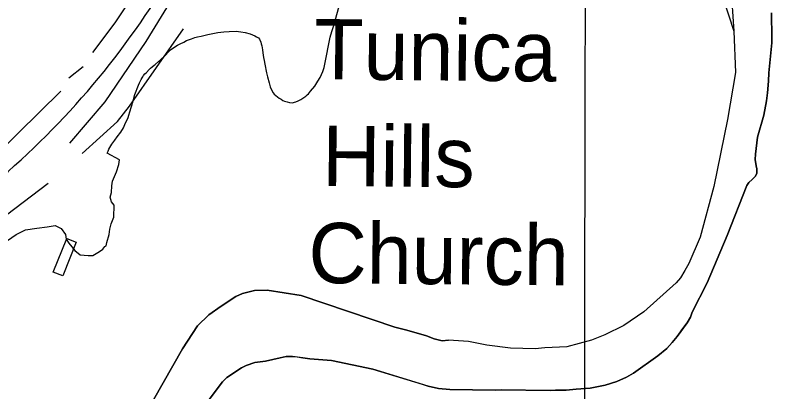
# Model space of a CAD drawing. Extents: x 3192986 to 3230865, y 867483 to 892886.
# Drawn here: x 3217338 to 3218379, y 886066 to 886585 of the extents above; entities that cross this region are included whole.
import ezdxf

# ---------------------------------------------------------------- set-up
doc = ezdxf.new("R2010")
doc.units = 0
for name, color, linetype in [('V-BLDG-OTLN', 7, 'Continuous'), ('V-GRID-MAJR', 7, 'Continuous'), ('V-ROAD-CNTR', 7, 'Continuous'), ('V-SITE-OTLN-IDEN', 7, 'Continuous'), ('V-SITE-VEGE', 7, 'Continuous'), ('V-TOPO-SHOR', 7, 'Continuous')]:
    doc.layers.add(name, color=color, linetype=linetype)

msp = doc.modelspace()

# ---------------------------------------------------------------- linework, layer by layer
at = {"layer": 'V-BLDG-OTLN'}
msp.add_lwpolyline([(3217422.247118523, 886272.3664276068), (3217403.836155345, 886225.8805205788), (3217390.820181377, 886231.035510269), (3217409.2311445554, 886277.5224172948)], close=True, dxfattribs=at)
at = {"layer": 'V-GRID-MAJR'}
msp.add_spline([(3218098.305, 872881.337), (3218108.882, 878940.914), (3218119.463, 885003.5750000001), (3218130.045, 891066.2810000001), (3218130.0500000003, 891069.3200000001)], degree=3, dxfattribs=at)
at = {"layer": 'V-ROAD-CNTR'}
msp.add_arc((3216590.678657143, 887208.6877788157), 1117.3858142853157, 308.27081185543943, 327.8519812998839, dxfattribs=at)
at = {"layer": 'V-SITE-VEGE'}
for p, q in [((3218120.414000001, 887211.4949999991), (3218326.171000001, 886562.636999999)), ((3217776.328000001, 886570.2949999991), (3217785.761000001, 886603.991999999)), ((3218377.999, 886587.9949999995), (3218378.196, 886576.0699999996)), ((3218378.196, 886576.0699999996), (3218378.542, 886565.1989999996)), ((3217616.9650000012, 886560.684999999), (3217625.449000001, 886561.952999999)), ((3217625.449000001, 886561.952999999), (3217632.712000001, 886562.4339999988)), ((3217632.712000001, 886562.4339999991), (3217642.184000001, 886562.476999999)), ((3217642.184000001, 886562.476999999), (3217648.420000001, 886561.768999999)), ((3217648.420000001, 886561.768999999), (3217654.648000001, 886560.6549999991)), ((3217771.625000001, 886554.2529999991), (3217773.770000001, 886562.0759999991)), ((3217773.770000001, 886562.0759999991), (3217776.328000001, 886570.2949999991)), ((3218326.171000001, 886562.636999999), (3218328.659000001, 886505.8929999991)), ((3218378.542, 886565.1989999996), (3218378.6550000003, 886556.0549999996)), ((3217574.057000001, 886549.7179999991), (3217580.750000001, 886552.224999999)), ((3217580.750000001, 886552.224999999), (3217585.208000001, 886553.7629999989)), ((3217585.208000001, 886553.7629999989), (3217589.056000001, 886554.9079999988)), ((3217589.056000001, 886554.9079999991), (3217593.908000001, 886555.8339999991)), ((3217593.908000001, 886555.8339999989), (3217603.016000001, 886558.0989999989)), ((3217603.016000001, 886558.0989999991), (3217616.9650000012, 886560.684999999)), ((3217654.648000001, 886560.6549999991), (3217661.2690000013, 886558.9319999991)), ((3217661.2690000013, 886558.9319999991), (3217664.677000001, 886557.866999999)), ((3217664.677000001, 886557.866999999), (3217667.880000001, 886556.4029999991)), ((3217667.880000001, 886556.4029999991), (3217670.272000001, 886554.9509999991)), ((3217670.272000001, 886554.9509999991), (3217672.668000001, 886553.7019999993)), ((3217672.668000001, 886553.7019999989), (3217674.448000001, 886551.6559999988)), ((3217674.448000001, 886551.6559999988), (3217676.193000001, 886547.596999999)), ((3217769.012000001, 886542.809999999), (3217771.625000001, 886554.2529999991)), ((3218378.6550000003, 886556.0549999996), (3218378.4930000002, 886546.5209999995)), ((3217552.080000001, 886536.9899999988), (3217557.792000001, 886541.1269999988)), ((3217557.792000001, 886541.1269999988), (3217561.458000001, 886543.4819999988)), ((3217561.458000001, 886543.481999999), (3217565.115000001, 886545.435999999)), ((3217565.115000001, 886545.4359999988), (3217570.397000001, 886547.7649999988)), ((3217570.397000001, 886547.7649999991), (3217574.057000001, 886549.7179999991)), ((3217676.193000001, 886547.596999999), (3217676.555000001, 886545.1699999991)), ((3217676.555000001, 886545.1699999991), (3217677.315000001, 886542.5399999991)), ((3217677.315000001, 886542.5399999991), (3217678.228000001, 886536.878999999)), ((3217766.358000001, 886528.748999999), (3217769.012000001, 886542.809999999)), ((3218378.4930000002, 886546.5209999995), (3218374.624, 886505.5159999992)), ((3217545.108000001, 886529.8529999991), (3217548.5980000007, 886533.6229999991)), ((3217548.598000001, 886533.6229999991), (3217552.080000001, 886536.9899999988)), ((3217678.228000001, 886536.878999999), (3217678.9700000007, 886533.0389999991)), ((3217678.970000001, 886533.0389999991), (3217679.865000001, 886526.3749999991)), ((3217530.985000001, 886516.988999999), (3217535.284000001, 886520.949999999)), ((3217535.284000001, 886520.949999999), (3217537.531000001, 886522.7259999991)), ((3217537.531000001, 886522.7259999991), (3217545.108000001, 886529.8529999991)), ((3217679.865000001, 886526.3749999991), (3217680.6040000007, 886522.3319999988)), ((3217680.604000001, 886522.3319999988), (3217681.731000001, 886517.476999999)), ((3217763.065000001, 886512.6819999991), (3217766.358000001, 886528.748999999)), ((3217518.708000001, 886505.9139999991), (3217522.6070000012, 886510.0789999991)), ((3217522.6070000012, 886510.0789999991), (3217524.446000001, 886511.6599999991)), ((3217524.446000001, 886511.6599999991), (3217526.898000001, 886513.6349999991)), ((3217526.898000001, 886513.6349999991), (3217529.353000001, 886515.809999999)), ((3217529.353000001, 886515.809999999), (3217530.985000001, 886516.988999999)), ((3217681.731000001, 886517.476999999), (3217683.944000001, 886505.3479999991)), ((3217761.359000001, 886507.0689999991), (3217763.065000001, 886512.6819999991)), ((3217512.736000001, 886498.356999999), (3217513.973000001, 886499.947999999)), ((3217513.973000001, 886499.947999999), (3217515.009000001, 886501.743999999)), ((3217515.009000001, 886501.743999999), (3217516.664000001, 886504.133999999)), ((3217516.664000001, 886504.133999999), (3217518.708000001, 886505.9139999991)), ((3217683.944000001, 886505.3479999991), (3217685.2590000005, 886499.6839999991)), ((3217685.259000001, 886499.6839999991), (3217687.539000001, 886491.3829999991)), ((3217754.684000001, 886493.881999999), (3217757.593000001, 886498.868999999)), ((3217757.593000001, 886498.868999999), (3217761.359000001, 886507.0689999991)), ((3218328.659000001, 886505.8929999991), (3218317.628000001, 886440.8999999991)), ((3218374.624, 886505.5159999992), (3218374.028, 886493.8689999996)), ((3217502.883000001, 886475.5499999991), (3217507.937000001, 886488.562999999)), ((3217507.937000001, 886488.562999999), (3217509.402000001, 886491.763999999)), ((3217509.402000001, 886491.763999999), (3217511.486000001, 886495.957999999)), ((3217511.486000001, 886495.957999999), (3217512.736000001, 886498.356999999)), ((3217687.539000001, 886491.3829999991), (3217689.062000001, 886486.1179999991)), ((3217750.341000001, 886487.1009999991), (3217751.793000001, 886489.4949999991)), ((3217751.793000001, 886489.4949999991), (3217754.684000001, 886493.881999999)), ((3218374.028, 886493.8689999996), (3218372.8340000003, 886477.9909999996)), ((3217689.062000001, 886486.1179999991), (3217690.6070000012, 886482.060999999)), ((3217690.6070000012, 886482.060999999), (3217693.156000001, 886477.986999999)), ((3217693.156000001, 886477.986999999), (3217694.537000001, 886476.1499999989)), ((3217741.4990000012, 886476.569999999), (3217744.575000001, 886479.944999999)), ((3217744.575000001, 886479.944999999), (3217750.341000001, 886487.1009999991)), ((3218372.8340000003, 886477.9909999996), (3218371.19, 886466.7579999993)), ((3217499.659000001, 886463.712999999), (3217501.380000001, 886470.1329999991)), ((3217501.380000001, 886470.1329999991), (3217501.816000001, 886472.1419999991)), ((3217501.816000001, 886472.1419999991), (3217502.883000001, 886475.5499999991)), ((3217694.537000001, 886476.1499999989), (3217699.1060000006, 886472.2449999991)), ((3217699.106000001, 886472.2449999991), (3217701.295000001, 886470.5959999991)), ((3217701.295000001, 886470.5959999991), (3217703.892000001, 886469.1419999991)), ((3217703.892000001, 886469.1419999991), (3217706.483000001, 886467.484999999)), ((3217727.231000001, 886466.9339999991), (3217730.8870000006, 886468.6869999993)), ((3217730.887000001, 886468.6869999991), (3217733.938000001, 886470.449999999)), ((3217733.938000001, 886470.449999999), (3217738.018000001, 886473.202999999)), ((3217738.018000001, 886473.202999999), (3217739.8630000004, 886475.187999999)), ((3217739.863000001, 886475.1879999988), (3217741.4990000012, 886476.569999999)), ((3217496.026000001, 886451.481999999), (3217497.744000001, 886457.699999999)), ((3217497.744000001, 886457.699999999), (3217499.020000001, 886461.709999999)), ((3217499.020000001, 886461.709999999), (3217499.659000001, 886463.712999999)), ((3217706.483000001, 886467.484999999), (3217708.6780000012, 886466.2399999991)), ((3217708.6780000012, 886466.2399999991), (3217712.295000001, 886465.5739999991)), ((3217712.295000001, 886465.5739999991), (3217715.703000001, 886464.508999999)), ((3217715.703000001, 886464.508999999), (3217719.322000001, 886464.045999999)), ((3217719.322000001, 886464.045999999), (3217724.382000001, 886465.3729999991)), ((3217724.382000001, 886465.3729999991), (3217727.231000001, 886466.9339999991)), ((3218371.19, 886466.7579999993), (3218367.6820000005, 886447.2099999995)), ((3217493.480000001, 886443.866999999), (3217494.545000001, 886447.2729999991)), ((3217494.545000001, 886447.2729999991), (3217496.026000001, 886451.481999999)), ((3218367.682, 886447.2099999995), (3218358.6890000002, 886416.7579999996)), ((3217489.282000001, 886434.0639999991), (3217493.480000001, 886443.866999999)), ((3218317.628000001, 886440.8999999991), (3218298.723000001, 886348.7459999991)), ((3217483.666000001, 886423.4779999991), (3217487.398000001, 886429.6599999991)), ((3217487.398000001, 886429.6599999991), (3217489.282000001, 886434.0639999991)), ((3217475.218000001, 886412.5349999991), (3217478.7290000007, 886417.312999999)), ((3217478.729000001, 886417.312999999), (3217483.666000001, 886423.4779999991)), ((3218358.6890000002, 886416.7579999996), (3218356.176, 886393.3509999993)), ((3217467.354000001, 886400.172999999), (3217471.2960000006, 886406.9579999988)), ((3217471.296000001, 886406.9579999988), (3217475.218000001, 886412.5349999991)), ((3217464.956000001, 886394.8609999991), (3217466.097000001, 886397.373999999)), ((3217481.754000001, 886385.6159999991), (3217464.956000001, 886394.8609999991)), ((3217466.097000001, 886397.373999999), (3217467.354000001, 886400.172999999)), ((3217480.744000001, 886379.2019999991), (3217481.754000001, 886385.6159999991)), ((3218356.176, 886393.3509999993), (3218355.924, 886386.2039999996)), ((3218355.924, 886386.2039999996), (3218357.099, 886377.4389999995)), ((3217477.844000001, 886369.1419999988), (3217480.744000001, 886379.2019999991)), ((3218357.099, 886377.4389999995), (3218357.822, 886373.1869999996)), ((3217472.148000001, 886356.3609999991), (3217477.844000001, 886369.1419999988)), ((3218358.115, 886366.9569999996), (3218355.793, 886362.7559999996)), ((3218357.822, 886373.1869999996), (3218358.115, 886366.9569999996)), ((3217471.139000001, 886349.9459999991), (3217472.148000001, 886356.3609999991)), ((3218347.044, 886354.5559999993), (3218344.056, 886350.2329999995)), ((3218351.75, 886358.7179999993), (3218347.044, 886354.5559999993)), ((3218355.793, 886362.7559999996), (3218351.75, 886358.7179999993)), ((3217471.008000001, 886340.7629999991), (3217471.139000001, 886349.9459999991)), ((3218298.723000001, 886348.7459999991), (3218280.193000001, 886278.9769999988)), ((3218344.056, 886350.2329999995), (3218317.065, 886281.5349999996)), ((3217469.079000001, 886334.3609999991), (3217471.008000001, 886340.7629999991)), ((3217470.821000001, 886327.905999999), (3217469.079000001, 886334.3609999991)), ((3217474.430000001, 886323.260999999), (3217470.821000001, 886327.905999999)), ((3217474.192000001, 886306.7309999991), (3217474.430000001, 886323.260999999)), ((3217470.387000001, 886297.5989999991), (3217474.192000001, 886306.7309999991)), ((3217352.695000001, 886289.185999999), (3217368.346000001, 886291.7169999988)), ((3217368.346000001, 886291.716999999), (3217382.147000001, 886293.3559999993)), ((3217382.147000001, 886293.3559999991), (3217393.194000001, 886295.0329999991)), ((3217393.194000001, 886295.0329999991), (3217401.406000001, 886291.241999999)), ((3217401.406000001, 886291.241999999), (3217407.716000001, 886282.883999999)), ((3217468.446000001, 886290.2799999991), (3217470.387000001, 886297.5989999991)), ((3217320.263000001, 886269.442999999), (3217339.745000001, 886282.9419999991)), ((3217339.745000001, 886282.9419999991), (3217352.695000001, 886289.185999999)), ((3217407.716000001, 886282.883999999), (3217408.542000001, 886276.442999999)), ((3217464.507000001, 886271.966999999), (3217467.422000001, 886282.947999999)), ((3217467.422000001, 886282.947999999), (3217468.446000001, 886290.2799999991)), ((3218317.065, 886281.5349999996), (3218289.872, 886216.4149999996)), ((3217408.542000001, 886276.442999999), (3217412.136000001, 886270.8829999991)), ((3217412.136000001, 886270.8829999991), (3217420.256000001, 886260.6599999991)), ((3217463.524000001, 886267.386999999), (3217464.507000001, 886271.966999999)), ((3218280.193000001, 886278.9769999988), (3218264.352000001, 886242.810999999)), ((3217420.256000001, 886260.6599999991), (3217427.527000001, 886255.045999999)), ((3217454.222000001, 886259.2549999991), (3217458.865000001, 886262.8609999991)), ((3217458.865000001, 886262.8609999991), (3217461.675000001, 886266.4939999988)), ((3217461.675000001, 886266.4939999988), (3217463.524000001, 886267.386999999)), ((3217427.527000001, 886255.045999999), (3217438.531000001, 886253.9689999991)), ((3217438.531000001, 886253.9689999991), (3217444.959000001, 886253.876999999)), ((3217444.959000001, 886253.8769999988), (3217454.222000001, 886259.2549999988)), ((3218264.352000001, 886242.810999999), (3218259.152000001, 886233.094999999)), ((3218259.152000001, 886233.094999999), (3218253.1590000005, 886223.3919999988)), ((3218253.159000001, 886223.3919999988), (3218247.081000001, 886216.4739999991)), ((3218247.081000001, 886216.4739999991), (3218202.8200000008, 886176.2819999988)), ((3218289.872, 886216.4149999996), (3218268.923, 886176.0979999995)), ((3217641.819000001, 886197.562999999), (3217621.632000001, 886184.2549999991)), ((3217651.078000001, 886201.8289999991), (3217641.819000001, 886197.562999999)), ((3217667.530000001, 886205.5929999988), (3217651.078000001, 886201.8289999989)), ((3217684.735000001, 886206.145999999), (3217667.530000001, 886205.5929999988)), ((3217731.417000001, 886198.6769999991), (3217684.735000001, 886206.145999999)), ((3217860.371000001, 886155.2349999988), (3217731.417000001, 886198.6769999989)), ((3217621.632000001, 886184.2549999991), (3217604.6600000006, 886172.1019999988)), ((3218202.820000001, 886176.2819999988), (3218175.213000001, 886157.5369999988)), ((3217604.660000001, 886172.1019999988), (3217589.2490000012, 886157.1249999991)), ((3218266.822, 886169.2429999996), (3218262.185, 886161.3719999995)), ((3218268.923, 886176.0979999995), (3218266.822, 886169.2429999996)), ((3217589.2490000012, 886157.1249999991), (3217568.398000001, 886125.4299999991)), ((3218175.213000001, 886157.5369999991), (3218149.0350000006, 886144.8609999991)), ((3218262.185, 886161.3719999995), (3218248.617, 886142.3919999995)), ((3217876.706000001, 886150.998999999), (3217860.371000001, 886155.2349999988)), ((3217903.793000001, 886143.4139999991), (3217876.706000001, 886150.998999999)), ((3217914.531000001, 886139.2579999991), (3217903.793000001, 886143.4139999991)), ((3217925.293000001, 886136.7039999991), (3217914.531000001, 886139.2579999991)), ((3217934.181000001, 886137.1689999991), (3217925.293000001, 886136.7039999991)), ((3217961.815000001, 886135.5619999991), (3217934.181000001, 886137.1689999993)), ((3217986.772000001, 886130.633999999), (3217961.815000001, 886135.5619999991)), ((3218130.628000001, 886137.4889999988), (3218096.686000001, 886128.1229999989)), ((3218149.035000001, 886144.8609999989), (3218130.628000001, 886137.4889999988)), ((3218248.617, 886142.3919999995), (3218241.586, 886134.0319999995)), ((3217568.398000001, 886125.4299999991), (3217528.597000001, 886055.2139999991)), ((3218019.554000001, 886126.2429999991), (3217986.772000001, 886130.633999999)), ((3218053.060000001, 886125.6799999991), (3218019.554000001, 886126.2429999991)), ((3218066.324000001, 886126.648999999), (3218053.060000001, 886125.6799999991)), ((3218096.686000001, 886128.1229999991), (3218066.324000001, 886126.6489999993)), ((3218234.0330000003, 886126.0769999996), (3218221.94, 886115.9479999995)), ((3218241.586, 886134.0319999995), (3218234.0330000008, 886126.0769999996)), ((3217710.8140000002, 886114.8809999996), (3217702.839, 886113.2919999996)), ((3217719.563, 886115.1309999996), (3217710.8140000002, 886114.8809999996)), ((3217733.703, 886113.0379999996), (3217719.563, 886115.1309999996)), ((3218221.94, 886115.9479999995), (3218188.287, 886092.1359999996)), ((3217667.751, 886106.4639999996), (3217655.895, 886102.6889999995)), ((3217682.353, 886108.3369999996), (3217667.751, 886106.4639999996)), ((3217702.839, 886113.2919999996), (3217682.353, 886108.3369999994)), ((3217743.617, 886111.8109999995), (3217733.703, 886113.0379999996)), ((3217773.252, 886109.3249999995), (3217743.617, 886111.8109999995)), ((3217830.284, 886097.5009999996), (3217773.252, 886109.3249999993)), ((3217649.35, 886099.4859999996), (3217629.2460000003, 886085.7829999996)), ((3217655.895, 886102.6889999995), (3217649.35, 886099.4859999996)), ((3217905.937, 886074.2359999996), (3217830.284, 886097.5009999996)), ((3217629.2460000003, 886085.7829999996), (3217623.3200000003, 886079.9209999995)), ((3218178.788, 886086.5999999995), (3218165.433, 886080.4659999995)), ((3218188.287, 886092.1359999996), (3218178.788, 886086.5999999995)), ((3217623.3200000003, 886079.9209999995), (3217605.162, 886055.8489999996)), ((3217920.3200000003, 886070.9469999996), (3217905.937, 886074.2359999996)), ((3218149.588, 886075.4339999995), (3218128.981, 886071.1419999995)), ((3218165.433, 886080.4659999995), (3218149.588, 886075.4339999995)), ((3217935.793, 886069.3619999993), (3217920.3200000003, 886070.9469999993)), ((3217998.312, 886068.5729999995), (3217935.793, 886069.3619999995)), ((3218006.4, 886068.9689999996), (3217998.312, 886068.5729999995)), ((3218073.949, 886068.0959999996), (3218006.4, 886068.9689999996)), ((3218080.9760000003, 886068.3749999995), (3218073.949, 886068.0959999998)), ((3218095.68, 886068.3909999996), (3218080.9760000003, 886068.3749999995)), ((3218109.748, 886069.8779999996), (3218095.68, 886068.3909999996)), ((3218128.981, 886071.1419999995), (3218109.748, 886069.8779999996))]:
    msp.add_line(p, q, dxfattribs=at)
at = {"layer": 'V-TOPO-SHOR'}
msp.add_line((3217431.7662633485, 886513.6961537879), (3217411.9802675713, 886497.8277448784), dxfattribs=at)
for points in [[(3217763.70988387, 887061.9051484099), (3217522.2794812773, 886644.8748057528), (3217475.18610981, 886573.9495221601), (3217444.4492709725, 886533.2032217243)], [(3217588.4963949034, 886663.8588839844), (3217517.7691727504, 886548.5486409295), (3217461.6314526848, 886465.2192775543), (3217412.893081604, 886408.5871352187)], [(3218322.296000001, 886623.6429999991), (3218326.171000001, 886562.636999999), (3218328.659000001, 886505.8929999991), (3218317.628000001, 886440.8999999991), (3218298.723000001, 886348.7459999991), (3218280.193000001, 886278.976999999), (3218264.350000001, 886242.810999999), (3218259.152000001, 886233.094999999), (3218253.159000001, 886223.3919999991), (3218247.081000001, 886216.4739999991), (3218202.820000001, 886176.2819999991), (3218175.213000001, 886157.5369999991), (3218149.033000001, 886144.8609999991), (3218130.628000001, 886137.488999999), (3218096.686000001, 886128.1229999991), (3218066.324000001, 886126.648999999), (3218053.060000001, 886125.6799999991), (3218019.552000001, 886126.2429999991), (3217986.772000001, 886130.635999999), (3217961.815000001, 886135.5619999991), (3217934.181000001, 886137.1689999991)], [(3217605.162000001, 886055.8489999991), (3217623.320000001, 886079.920999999), (3217629.246000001, 886085.7829999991), (3217649.350000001, 886099.4859999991), (3217655.895000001, 886102.6889999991), (3217667.751000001, 886106.4639999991), (3217682.353000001, 886108.336999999), (3217702.839000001, 886113.2919999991), (3217710.814000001, 886114.8809999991), (3217719.563000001, 886115.1309999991), (3217725.906000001, 886114.229999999), (3217733.703000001, 886113.037999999), (3217743.617000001, 886111.810999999), (3217773.252000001, 886109.324999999), (3217830.284000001, 886097.5009999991), (3217897.897000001, 886076.7549999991), (3217905.935000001, 886074.2359999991), (3217920.320000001, 886070.9469999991), (3217935.793000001, 886069.361999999), (3217998.312000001, 886068.572999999), (3218006.400000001, 886068.9689999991), (3218073.949000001, 886068.0959999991), (3218080.976000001, 886068.3749999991), (3218095.680000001, 886068.390999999), (3218109.748000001, 886069.8779999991), (3218128.981000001, 886071.143999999), (3218149.588000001, 886075.4339999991), (3218165.435000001, 886080.4659999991), (3218178.788000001, 886086.599999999), (3218188.287000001, 886092.1379999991), (3218221.940000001, 886115.947999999), (3218234.033000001, 886126.0769999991), (3218241.586000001, 886134.0319999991), (3218248.617000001, 886142.3919999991), (3218256.350000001, 886153.2559999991), (3218262.185000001, 886161.371999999), (3218266.822000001, 886169.2429999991), (3218268.923000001, 886176.0979999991), (3218289.872000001, 886216.4149999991), (3218317.065000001, 886281.5349999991), (3218344.056000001, 886350.234999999), (3218347.044000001, 886354.555999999), (3218351.750000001, 886358.7179999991), (3218355.793000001, 886362.7559999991), (3218358.115000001, 886366.9569999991), (3218357.822000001, 886373.1869999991), (3218357.099000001, 886377.4389999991), (3218355.924000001, 886386.2039999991), (3218356.176000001, 886393.3509999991), (3218358.689000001, 886416.7579999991), (3218367.682000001, 886447.209999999), (3218371.190000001, 886466.7579999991), (3218372.834000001, 886477.9909999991), (3218374.030000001, 886493.868999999), (3218374.6240000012, 886505.515999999), (3218378.493000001, 886546.520999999), (3218378.655000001, 886556.0569999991), (3218378.542000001, 886565.1989999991), (3218378.196000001, 886576.069999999), (3218377.9990000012, 886587.9949999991)], [(3217430.598253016, 886394.1370970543), (3217479.214593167, 886438.2779946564), (3217495.4839608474, 886459.5346601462), (3217569.692945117, 886565.8877195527)], [(3217401.099156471, 886480.0877074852), (3217312.806226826, 886393.503210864), (3217228.2739871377, 886326.5129471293), (3217118.741824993, 886257.9822817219), (3217095.3520361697, 886238.5798117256)], [(3216979.472802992, 886068.3870238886), (3217072.578700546, 886099.6008520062), (3217140.597510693, 886120.3519607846), (3217153.454848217, 886157.7036640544), (3217177.0363999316, 886196.7352329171), (3217383.801242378, 886353.5476935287)], [(3217528.597000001, 886055.2139999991), (3217568.396000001, 886125.4299999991), (3217589.2490000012, 886157.1249999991), (3217604.660000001, 886172.101999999), (3217621.632000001, 886184.2549999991), (3217641.819000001, 886197.562999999), (3217651.078000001, 886201.8289999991), (3217667.530000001, 886205.5929999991), (3217684.735000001, 886206.145999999), (3217731.417000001, 886198.6769999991), (3217860.371000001, 886155.234999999), (3217876.706000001, 886150.998999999), (3217903.793000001, 886143.4139999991), (3217914.531000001, 886139.2579999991), (3217925.293000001, 886136.7039999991), (3217934.181000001, 886137.1689999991)]]:
    msp.add_lwpolyline(points, dxfattribs=at)

# ---------------------------------------------------------------- texts
at = {"layer": 'V-SITE-OTLN-IDEN'}
for s, p in [('Tunica ', (3217749.234162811, 886496.5540864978)), (' Hills ', (3217729.320405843, 886350.0581801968)), ('Church', (3217741.251000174, 886216.1562721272))]:
    msp.add_text(s, height=82.999832, rotation=359.4402771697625, dxfattribs=at).set_placement(p)

doc.saveas('drawing.dxf')
